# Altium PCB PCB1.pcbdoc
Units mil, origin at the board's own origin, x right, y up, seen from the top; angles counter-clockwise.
Board outline 4130 x 3879.64 mil, 2 copper layers (Top Layer, Bottom Layer); 142 components, 79 nets, 510 pads, 190 vias.
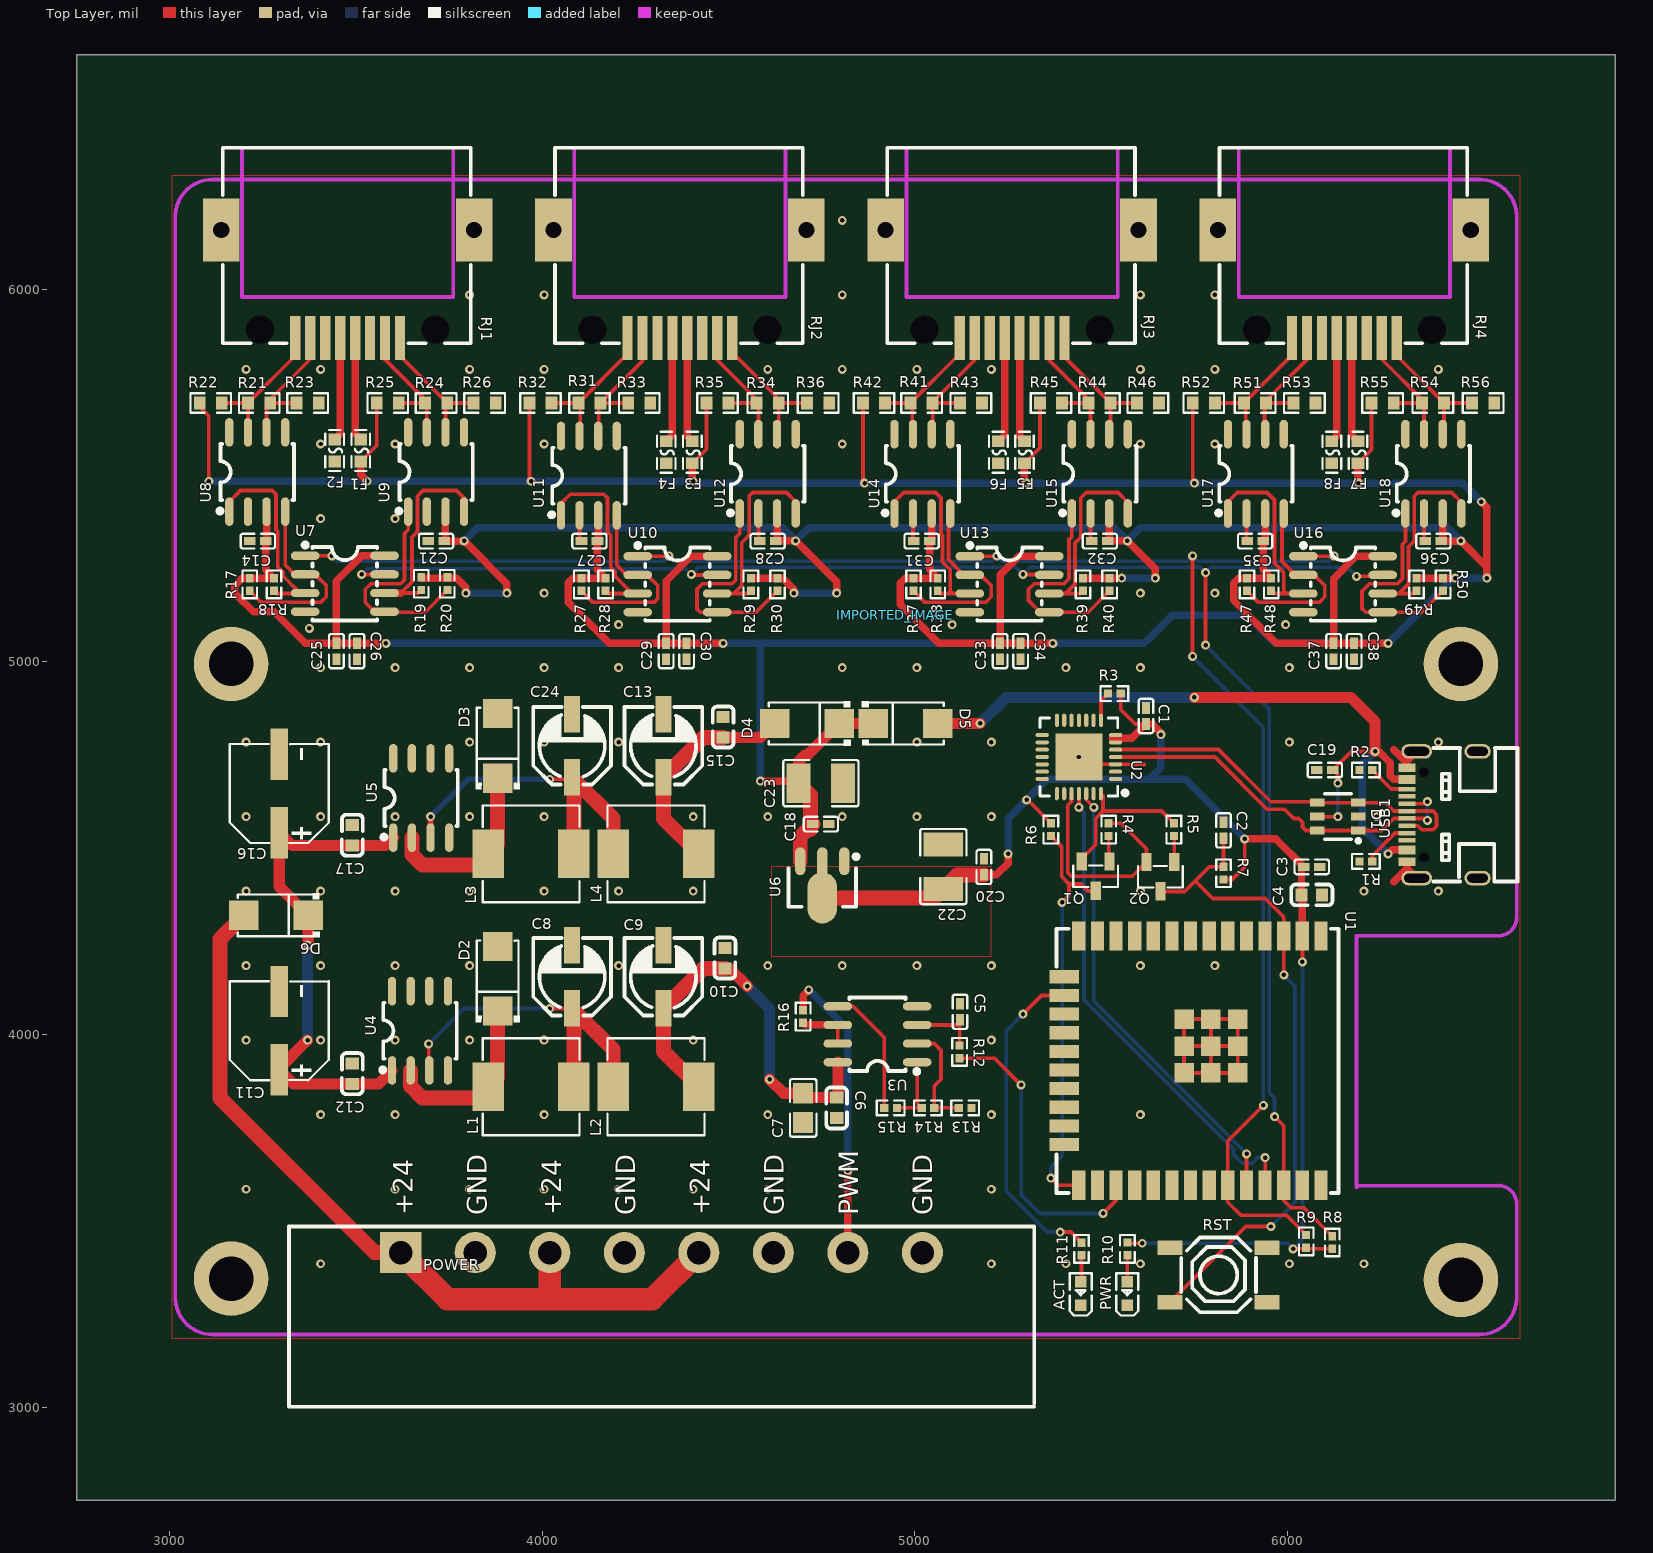
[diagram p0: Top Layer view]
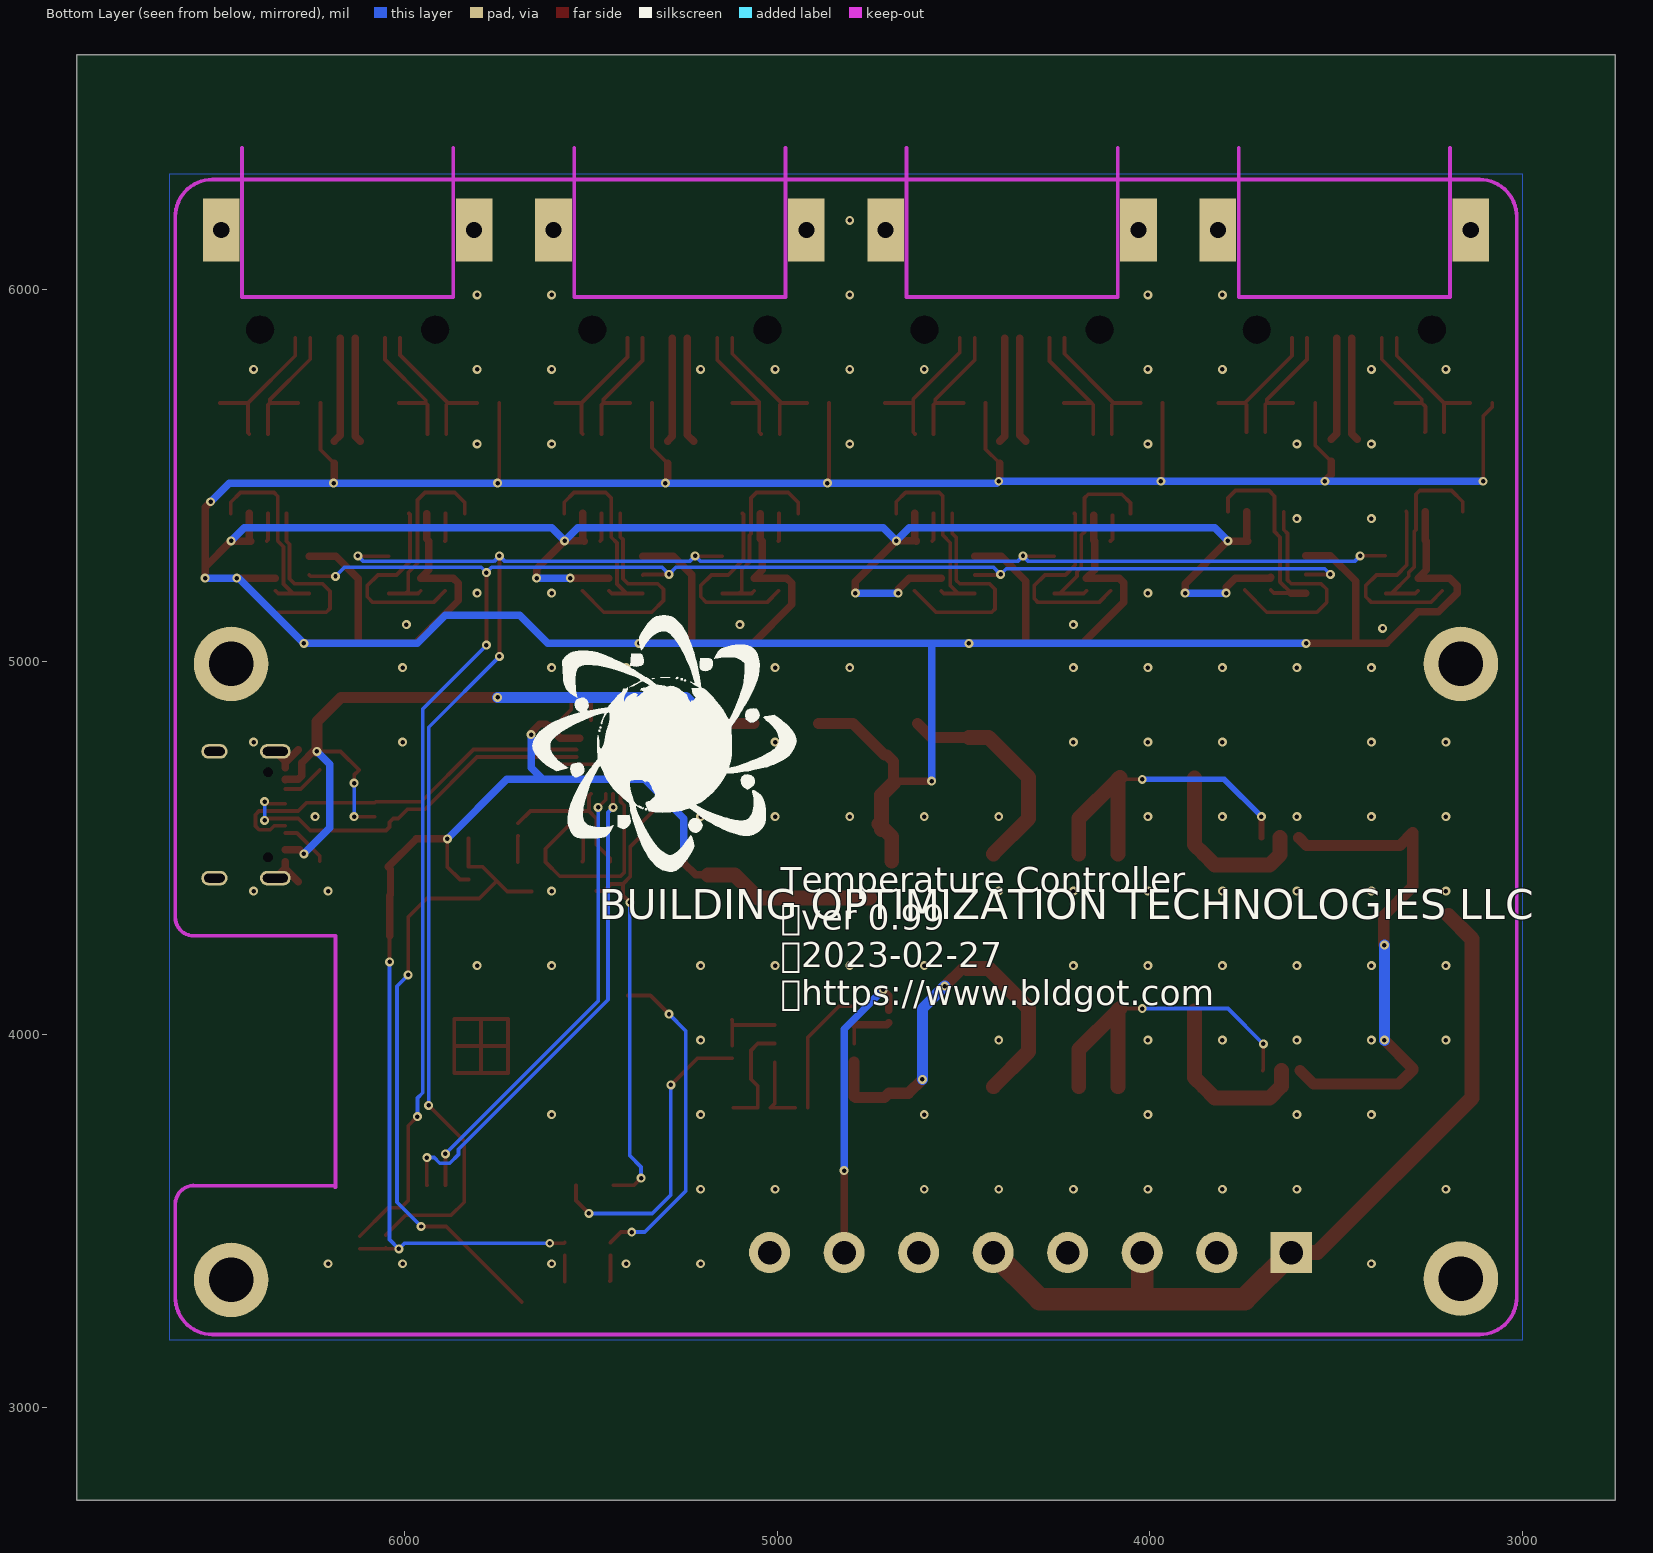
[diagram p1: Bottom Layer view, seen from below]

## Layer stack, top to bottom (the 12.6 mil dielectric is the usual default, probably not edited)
Top Layer: signal copper (thickness not stored)
Dielectric: dielectric 12.6, FR-4, Dk 4.8
Bottom Layer: signal copper (thickness not stored)

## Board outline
6880,2750 2750,2750 2750,6629.64 6880,6629.64

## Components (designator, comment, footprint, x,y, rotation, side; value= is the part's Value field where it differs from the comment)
ACT "19-217/BHC-ZL1M2RY/3T" LED0603-RD 5445,3304.45 r90 top
C1 "CAP_0402" C0402 5620,4854.45 r90 top
C2 "CAP_0402" C0402 5828.08,4547.53 r90 top
C3 "CAP_0402" C0402 6065,4449.45 r0 top
C4 "CL10A106KP8NNNC" C0603 6065,4374.45 r180 top
C5 "CAP_0402" C0402 5121.04,4060.68 r90 top
C6 "CC0603KRX7R9BB104" C0603 4789.94,3802.91 r90 top
C7 "GRM21BR61H106KE43L" C0805 4699.94,3802.91 r90 top
C8 "CK1C470M-CRD54" CAP-SMD_BD5.0-L5.3-W5.3-RD 4080,4154.45 r270 top
C9 "CK1C470M-CRD54" CAP-SMD_BD5.0-L5.3-W5.3-RD 4325,4154.45 r270 top
C10 "CC0603KRX7R9BB104" C0603 4490,4204.45 r270 top
C11 "CS1H470M-CRE77" CAP-SMD_BD6.3-L6.6-W6.6-FD 3294.05,4009.89 r90 top
C12 "CC0603KRX7R9BB104" C0603 3490,3894.45 r270 top
C13 "CS1A101M-CRD54" CAP-SMD_BD5.0-L5.3-W5.3-RD 4325,4774.45 r270 top
C14 "CAP_0402" C0402 3236.58,5323.89 r0 top
C15 "CC0603KRX7R9BB104" C0603 4485,4824.45 r270 top
C16 "CS1H470M-CRE77" CAP-SMD_BD6.3-L6.6-W6.6-FD 3294.05,4646.35 r90 top
C17 "CC0603KRX7R9BB104" C0603 3490,4534.45 r270 top
C18 "CAP_0402" C0402 4747.61,4564.21 r0 top
C19 "CAP_0402" C0402 6100,4709.45 r180 top
C20 "CAP_0402" C0402 5185,4449.45 r90 top
C21 "CAP_0402" C0402 3714.9,5323.89 r0 top
C22 "JMK325BJ107MM-T" C1210 5076.35,4450.47 r270 top
C23 "HMK325C7475KMHPE" C1210 4747.61,4674.21 r180 top
C24 "CS1A101M-CRD54" CAP-SMD_BD5.0-L5.3-W5.3-RD 4080,4774.45 r270 top
C25 "CAP_0402" C0402 3447.37,5028.61 r90 top
C26 "CAP_0402" C0402 3502.37,5028.61 r270 top
C27 "CAP_0402" C0402 4126.58,5323.89 r0 top
C28 "CAP_0402" C0402 4604.9,5323.89 r0 top
C29 "CAP_0402" C0402 4332.37,5028.61 r90 top
C30 "CAP_0402" C0402 4387.37,5028.61 r270 top
C31 "CAP_0402" C0402 5017.91,5323.89 r0 top
C32 "CAP_0402" C0402 5496.24,5323.89 r0 top
C33 "CAP_0402" C0402 5228.71,5028.61 r90 top
C34 "CAP_0402" C0402 5283.71,5028.61 r270 top
C35 "CAP_0402" C0402 5912.91,5323.89 r0 top
C36 "CAP_0402" C0402 6391.24,5323.89 r0 top
C37 "CAP_0402" C0402 6123.71,5028.61 r90 top
C38 "CAP_0402" C0402 6178.71,5028.61 r270 top
D1 "USBLC6-2SC6_C7519" SOT-23-6_L2.9-W1.6-P0.95-LS2.8-BR 6135,4584.45 r0 top
D2 "SS34_C8678" SMA_L4.3-W2.6-LS5.2-RD 3880,4149.45 r90 top
D3 "SS34_C8678" SMA_L4.3-W2.6-LS5.2-RD 3880,4774.45 r90 top
D4 "SS34_C8678" SMA_L4.3-W2.6-LS5.2-RD 4710,4834.45 r180 top
D5 "SS34_C8678" SMA_L4.3-W2.6-LS5.2-RD 4975,4834.45 r0 top
D6 "SS34_C8678" SMA_L4.3-W2.6-LS5.2-RD 3285,4319.45 r180 top
F1 "0494001.NR" F0603 3512.64,5567.23 r90 top
F2 "0494001.NR" F0603 3442.64,5567.23 r90 top
F3 "0494001.NR" F0603 4402.64,5562.23 r90 top
F4 "0494001.NR" F0603 4332.64,5562.23 r90 top
F5 "0494001.NR" F0603 5293.97,5562.23 r90 top
F6 "0494001.NR" F0603 5223.97,5562.23 r90 top
F7 "0494001.NR" F0603 6188.97,5562.23 r90 top
F8 "0494001.NR" F0603 6118.97,5562.23 r90 top
IMPORTED_IMAGE "IMPORTED_IMAGE" IMPORTED_IMAGE 4947.73,5124.45 r0 top
L1 "SMMS0650-680M" IND-SMD_L7.1-W6.6 3970,3859.45 r180 top
L2 "SMMS0650-680M" IND-SMD_L7.1-W6.6 4305,3859.45 r180 top
L3 "SMMS0650-680M" IND-SMD_L7.1-W6.6 3970,4484.45 r180 top
L4 "SMMS0650-680M" IND-SMD_L7.1-W6.6 4305,4484.45 r180 top
POWER "2ETYRM-5.08-08P-14-00AH" CONN-TH_2ETYRM-5.08-08P-14-00AH 4320,3414.45 r0 top
PWR "19-217/GHC-YR1S2/3T" LED0603-RD 5570,3304.45 r90 top
Q1 "S9013 J3_C6749" SOT-23-3_L2.9-W1.3-P1.90-LS2.4-BR 5485,4424.45 r90 top
Q2 "S9013 J3_C6749" SOT-23-3_L2.9-W1.3-P1.90-LS2.4-BR 5658.87,4423.11 r90 top
R1 "Res_0402" R0402 6210,4464.45 r0 top
R2 "Res_0402" R0402 6210,4709.45 r180 top
R3 "Res_0402" R0402 5535,4914.45 r180 top
R4 "Res_0402" R0402 5520,4549.45 r270 top
R5 "Res_0402" R0402 5695,4549.45 r270 top
R6 "Res_0402" R0402 5365,4549.45 r90 top
R7 "Res_0402" R0402 5828.08,4432.53 r270 top
R8 "Res_0402" R0402 6120,3441.49 r270 top
R9 "Res_0402" R0402 6050,3444.45 r270 top
R10 "Res_0402" R0402 5570,3424.45 r90 top
R11 "Res_0402" R0402 5447.14,3424.16 r90 top
R12 "Res_0402" R0402 5119.94,3952.91 r90 top
R13 "AR02BTC1002" R0402 5134.94,3802.91 r180 top
R14 "AR02BTC1002" R0402 5034.94,3802.91 r180 top
R15 "Res_0402" R0402 4934.94,3802.91 r180 top
R16 "Res_0402" R0402 4699.94,4047.91 r90 top
R17 "Res_0402" R0402 3214.85,5207.48 r90 top
R18 "Res_0402" R0402 3279.79,5207.48 r90 top
R19 "Res_0402" R0402 3675,5209.45 r90 top
R20 "Res_0402" R0402 3745,5209.45 r90 top
R21 "Res_0603" R0603 3240.19,5694.6 r180 top
R22 "Res_0603" R0603 3110.19,5694.6 r180 top
R23 "Res_0603" R0603 3370.19,5694.6 r180 top
R24 "Res_0603" R0603 3715.19,5694.6 r180 top
R25 "Res_0603" R0603 3585.19,5694.6 r180 top
R26 "Res_0603" R0603 3845.19,5694.6 r180 top
R27 "Res_0402" R0402 4104.85,5207.48 r90 top
R28 "Res_0402" R0402 4169.79,5207.48 r90 top
R29 "Res_0402" R0402 4559.74,5207.48 r90 top
R30 "Res_0402" R0402 4631.06,5207.48 r90 top
R31 "Res_0603" R0603 4126.58,5694.6 r180 top
R32 "Res_0603" R0603 3995.19,5694.6 r180 top
R33 "Res_0603" R0603 4260.19,5694.6 r180 top
R34 "Res_0603" R0603 4604.9,5694.6 r180 top
R35 "Res_0603" R0603 4470.19,5694.6 r180 top
R36 "Res_0603" R0603 4740.19,5694.6 r180 top
R37 "Res_0402" R0402 4996.19,5207.48 r90 top
R38 "Res_0402" R0402 5061.13,5207.48 r90 top
R39 "Res_0402" R0402 5451.08,5207.48 r90 top
R40 "Res_0402" R0402 5522.4,5207.48 r90 top
R41 "Res_0603" R0603 5017.91,5694.6 r180 top
R42 "Res_0603" R0603 4890.19,5694.6 r180 top
R43 "Res_0603" R0603 5150.19,5694.6 r180 top
R44 "Res_0603" R0603 5495.19,5694.6 r180 top
R45 "Res_0603" R0603 5365.19,5694.6 r180 top
R46 "Res_0603" R0603 5625.19,5694.6 r180 top
R47 "Res_0402" R0402 5891.19,5207.48 r90 top
R48 "Res_0402" R0402 5956.13,5207.48 r90 top
R49 "Res_0402" R0402 6346.08,5207.48 r90 top
R50 "Res_0402" R0402 6417.4,5207.48 r90 top
R51 "Res_0603" R0603 5912.91,5694.6 r180 top
R52 "Res_0603" R0603 5775.19,5694.6 r180 top
R53 "Res_0603" R0603 6045.19,5694.6 r180 top
R54 "Res_0603" R0603 6390.19,5694.6 r180 top
R55 "Res_0603" R0603 6255.19,5694.6 r180 top
R56 "Res_0603" R0603 6524.85,5694.6 r180 top
RJ1 "MJ88-B011-JRVS1-P" RJ45-SMD_MJ88-B011-JRVS1-P. 3477.64,6013.99 r180 top
RJ2 "MJ88-B011-JRVS1-P" RJ45-SMD_MJ88-B011-JRVS1-P. 4369.22,6013.99 r180 top
RJ3 "MJ88-B011-JRVS1-P" RJ45-SMD_MJ88-B011-JRVS1-P. 5260.81,6013.99 r180 top
RJ4 "MJ88-B011-JRVS1-P" RJ45-SMD_MJ88-B011-JRVS1-P. 6152.4,6013.99 r180 top
RST "TS-1187A-B-A-B" SW-SMD_4P-L5.1-W5.1-P3.70-LS6.5-TL-2 5815,3354.45 r180 top
U1 "ESP32-WROOM-32UE-N16_C701346" WIFI-SMD_ESP32-WROOM-32UE 5745,3929.45 r270 top
U2 "CP2102-GMR" WQFN-28_L5.0-W5.0-P0.50-BL-EP3.2 5439.99,4744.45 r90 top
U3 "LM358DR2G" SOIC-8_L5.0-W4.0-P1.27-LS6.0-BL 4899.68,4000.43 r90 top
U4 "XL1509-12E1" SOIC-8_L5.0-W4.0-P1.27-LS6.0-BL 3671.73,4009.71 r0 top
U5 "XL1509-5.0E1" SOIC-8_L5.0-W4.0-P1.27-LS6.0-BL 3675,4634.45 r0 top
U6 "AMS1117-3.3_C2904742" SOT-89-3_L4.5-W2.5-P1.50-LS4.1-BL 4751.35,4415.47 r180 top
U7 "P82B96D" SOIC-8_L5.0-W4.0-P1.27-LS6.1-BL 3470,5209.45 r270 top
U8 "PCA82C251T/YM,118" SOIC-8_L5.0-W4.0-P1.27-LS6.0-BL 3235,5509.45 r0 top
U9 "PCA82C251T/YM,118" SOIC-8_L5.0-W4.0-P1.27-LS6.0-BL 3715,5509.45 r0 top
U10 "P82B96D" SOIC-8_L5.0-W4.0-P1.27-LS6.1-BL 4362.64,5208.16 r270 top
U11 "PCA82C251T/YM,118" SOIC-8_L5.0-W4.0-P1.27-LS6.0-BL 4125,5499.45 r0 top
U12 "PCA82C251T/YM,118" SOIC-8_L5.0-W4.0-P1.27-LS6.0-BL 4604.9,5504.54 r0 top
U13 "P82B96D" SOIC-8_L5.0-W4.0-P1.27-LS6.1-BL 5253.97,5208.16 r270 top
U14 "PCA82C251T/YM,118" SOIC-8_L5.0-W4.0-P1.27-LS6.0-BL 5020,5504.45 r0 top
U15 "PCA82C251T/YM,118" SOIC-8_L5.0-W4.0-P1.27-LS6.0-BL 5496.24,5504.54 r0 top
U16 "P82B96D" SOIC-8_L5.0-W4.0-P1.27-LS6.1-BL 6148.97,5208.16 r270 top
U17 "PCA82C251T/YM,118" SOIC-8_L5.0-W4.0-P1.27-LS6.0-BL 5915,5504.45 r0 top
U18 "PCA82C251T/YM,118" SOIC-8_L5.0-W4.0-P1.27-LS6.0-BL 6391.24,5504.54 r0 top
USB1 "TYPEC-304-ACP16" USB-C-SMD_TYPE-C-16P-1 6415,4589.45 r90 top

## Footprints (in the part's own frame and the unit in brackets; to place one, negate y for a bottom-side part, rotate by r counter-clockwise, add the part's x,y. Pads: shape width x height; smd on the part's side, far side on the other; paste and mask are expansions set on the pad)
C0402 [mm]
  rect 0.79x0.54 smd: 1(-0.545,0) 2(0.545,0)
  silkscreen extent -1.17,-0.5 1.17,0.5
C0603 [mm]
  rect 0.8x0.9 smd: 1(-0.7,0) 2(0.7,0)
  silkscreen extent -1.41,-0.71 1.39,0.72
C0805 [mm]
  rect 1.41x1.35 smd: 1(-1,0) 2(1,0)
  silkscreen extent -1.96,-0.9 1.96,0.9
C1210 [mm]
  rect 1.635x2.7 smd: 1(-1.517,0) 2(1.517,0)
  silkscreen extent -2.56,-1.58 2.56,1.58
CAP-SMD_BD5.0-L5.3-W5.3-RD [mm]
  rect 2.5x1.1 smd: 1(2.15,0) 2(-2.15,0)
  silkscreen extent -2.65,-2.65 2.64,2.65
CAP-SMD_BD6.3-L6.6-W6.6-FD [mm]
  rect 3.5x1.2 smd: 1(-2.67,0) 2(2.67,0)
  silkscreen extent -3.38,-3.38 3.38,3.38
CONN-TH_2ETYRM-5.08-08P-14-00AH [mm]
  rect 2.8x2.8 hole 1.6: 1(-17.78,0)
  round 2.8 hole 1.6: 2(-12.7,0) 3(-7.62,0) 4(-2.54,0) 5(2.54,0) 6(7.62,0) 7(12.7,0) 8(17.78,0)
  silkscreen extent -25.4,-10.5 25.4,1.78
F0603 [mil]
  rect 31.75x34.02 smd: 1(-29.66,0) 2(29.66,0)
  silkscreen extent -55,-25 55,25
IMPORTED_IMAGE [mil]
IND-SMD_L7.1-W6.6 [mm]
  rect 2.15x3.32 smd: 1(-2.913,0) 2(2.913,0)
  silkscreen extent -3.3,-3.3 3.3,3.3
LED0603-RD [mm]
  rect 0.8x0.8 smd: 1(-0.799,-0.003) 2(0.799,0.003)
  silkscreen extent -1.49,-0.75 1.39,0.76
R0402 [mm]
  rect 0.566x0.54 smd: 1(-0.433,0) 2(0.433,0)
  silkscreen extent -0.94,-0.5 0.94,0.5
R0603 [mil]
  rect 31.75x34.02 smd: 1(-29.66,0) 2(29.66,0)
  silkscreen extent -55,-26 55,26
RJ45-SMD_MJ88-B011-JRVS1-P. [mm]
  rect 0.7x3 smd: 1(-3.57,3.684) 2(-2.55,3.684) 3(-1.53,3.684) 4(-0.51,3.684) 5(0.51,3.684) 6(1.53,3.684) 7(2.55,3.684) 8(3.57,3.684)
  rect 2.5x4.3 hole 1.1: 9(8.62,-3.684) 10(-8.62,-3.684)
  Board Outline Layer lines w0.254: 7.2,0.89 -7.2,0.89 ; 7.2,0.89 7.2,-9.271 7.2,0.89 ; 7.2,0.89 -7.2,0.89 ; -7.2,0.89 -7.2,-9.271 -7.2,0.89
  Multi-Layer board cut-out: -6.92,3.117 -6.826,2.704 -6.562,2.374 -6.181,2.19 -5.759,2.19 -5.378,2.374 -5.114,2.704 -5.02,3.117 -5.02,3.117 -5.114,3.529 -5.378,3.859 -5.759,4.043 -6.181,4.043 -6.562,3.859 -6.826,3.529 -6.92,3.117
  Multi-Layer board cut-out: 5.02,3.117 5.114,2.704 5.378,2.374 5.759,2.19 6.181,2.19 6.562,2.374 6.826,2.704 6.92,3.117 6.92,3.117 6.826,3.529 6.562,3.859 6.181,4.043 5.759,4.043 5.378,3.859 5.114,3.529 5.02,3.117
  silkscreen extent -8.38,-9.29 8.51,4.05
SMA_L4.3-W2.6-LS5.2-RD [mm]
  rect 2x2 smd: 1(-2.2,0) 2(2.2,0)
  silkscreen extent -2.98,-1.5 2.6,1.5
SOIC-8_L5.0-W4.0-P1.27-LS6.0-BL [mil]
  oval 22.38x76.78 smd: 1(-75,-106.5) 2(-25,-106.5) 3(25,-106.5) 4(75,-106.5) 5(75,106.5) 6(25,106.5) 7(-25,106.5) 8(-75,106.5)
  silkscreen extent -106,-111 98,75
SOIC-8_L5.0-W4.0-P1.27-LS6.1-BL [mil]
  oval 22.38x76.78 smd: 1(-75,-106.5) 2(-25,-106.5) 3(25,-106.5) 4(75,-106.5) 5(75,106.5) 6(25,106.5) 7(-25,106.5) 8(-75,106.5)
  silkscreen extent -110,-112 98,87
SOT-23-3_L2.9-W1.3-P1.90-LS2.4-BR [mm]
  rect 1.25x0.7 smd: 1(1,-0.95) 2(1,0.95) 3(-1,0)
  silkscreen extent -0.73,-1.53 0.73,1.53
SOT-23-6_L2.9-W1.6-P0.95-LS2.8-BR [mm]
  rect 1x0.55 smd: 1(1.4,-0.95) 2(1.4,0) 3(1.4,0.95) 4(-1.4,0.95) 5(-1.4,0) 6(-1.4,-0.95)
  silkscreen extent -0.9,-1.78 1.52,1.55
SOT-89-3_L4.5-W2.5-P1.50-LS4.1-BL [mm]
  oval 0.7x1.9 smd: 1(-1.501,-1.25) 3(1.501,-1.25)
  oval 2x3.5 smd: 2(0,1.25)
  oval 0.7x2.1 smd: 2(0,-1.151)
  silkscreen extent -2.46,-1.71 2.3,1.85
SW-SMD_4P-L5.1-W5.1-P3.70-LS6.5-TL-2 [mm]
  rect 1.7x1 smd: 1(-3.3,1.85) 2(3.3,1.85) 3(-3.3,-1.85) 4(3.3,-1.85)
  silkscreen extent -2.55,-2.55 2.55,2.55
USB-C-SMD_TYPE-C-16P-1 [mm]
  rect 0.6x1.15 smd: A1B12(-3.2,2.41) A4B9(-2.4,2.41) B1A12(3.2,2.41) B4A9(2.4,2.41)
  rect 0.3x1.15 smd: A5(-1.25,2.41) A6(-0.25,2.41) A7(0.25,2.41) A8(1.25,2.41) B5(1.75,2.41) B6(0.75,2.41) B7(-0.75,2.41) B8(-1.75,2.41)
  oval 1x1.8 hole 0.6 slot 1.4 at 90 deg: EP(-4.32,-2.41) EP(4.32,-2.41)
  oval 1x2.1 hole 0.6 slot 1.7 at 90 deg: EP(-4.32,1.74) EP(4.32,1.74)
  Multi-Layer board cut-out: -2.9,0.915 -2.759,0.947 -2.646,1.037 -2.583,1.168 -2.583,1.312 -2.646,1.443 -2.759,1.533 -2.9,1.565 -2.9,1.565 -3.041,1.533 -3.154,1.443 -3.217,1.312 -3.217,1.168 -3.154,1.037 -3.041,0.947 -2.9,0.915
  Multi-Layer board cut-out: 2.9,0.925 3.041,0.957 3.154,1.047 3.217,1.178 3.217,1.322 3.154,1.453 3.041,1.543 2.9,1.575 2.9,1.575 2.759,1.543 2.646,1.453 2.583,1.322 2.583,1.178 2.646,1.047 2.759,0.957 2.9,0.925
  silkscreen extent -4.55,-5.14 4.55,0.59
WIFI-SMD_ESP32-WROOM-32UE [mm]
  rect 2x0.9 smd: 1(-8.5,8.755) 2(-8.5,7.485) 3(-8.5,6.215) 4(-8.5,4.945) 5(-8.5,3.675) 6(-8.5,2.405) 7(-8.5,1.135) 8(-8.5,-0.135) 9(-8.5,-1.405) 10(-8.5,-2.675) 11(-8.5,-3.945) 12(-8.5,-5.215) 13(-8.5,-6.485) 14(-8.5,-7.755) 25(8.5,-7.755) 26(8.5,-6.485) 27(8.5,-5.215) 28(8.5,-3.945) 29(8.5,-2.675) 30(8.5,-1.405) 31(8.5,-0.135) 32(8.5,1.135) 33(8.5,2.405) 34(8.5,3.675) 35(8.5,4.945) 36(8.5,6.215) 37(8.5,7.485) 38(8.5,8.755)
  rect 0.9x2 smd: 15(-5.715,-8.755) 16(-4.445,-8.755) 17(-3.175,-8.755) 18(-1.905,-8.755) 19(-0.635,-8.755) 20(0.635,-8.755) 21(1.905,-8.755) 22(3.175,-8.755) 23(4.445,-8.755) 24(5.715,-8.755)
  rect 1.33x1.33 smd: 39(-2.835,3.09) 39(-2.835,1.255) 39(-2.835,-0.58) 39(-1,3.09) 39(-1,1.255) 39(-1,-0.58) 39(0.835,3.09) 39(0.835,1.255) 39(0.835,-0.58)
  silkscreen extent -9,-9.27 9.02,9.95
WQFN-28_L5.0-W5.0-P0.50-BL-EP3.2 [mm]
  oval 0.28x0.9 smd: 1(-1.501,-2.5) 2(-1.001,-2.5) 3(-0.501,-2.5) 4(0,-2.5) 5(0.5,-2.5) 6(1.001,-2.5) 7(1.501,-2.5) 15(1.501,2.5) 16(1.001,2.5) 17(0.5,2.5) 18(0,2.5) 19(-0.501,2.5) 20(-1.001,2.5) 21(-1.501,2.5)
  oval 0.9x0.28 smd: 8(2.5,-1.501) 9(2.5,-1.001) 10(2.5,-0.501) 11(2.5,0) 12(2.5,0.5) 13(2.5,1.001) 14(2.5,1.501) 22(-2.5,1.501) 23(-2.5,1.001) 24(-2.5,0.5) 25(-2.5,0) 26(-2.5,-0.501) 27(-2.5,-1.001) 28(-2.5,-1.501)
  rect 3.2x3.2 smd: 29(0,0)
  silkscreen extent -2.65,-3.3 2.65,2.65

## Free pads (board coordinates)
  round 200 hole 120: 1(3165,3344.45) 1(3165,4994.45) 1(6465,3341.21) 1(6465,4994.45)

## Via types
v1: diameter 24, hole 12, Top Layer to Bottom Layer, 107 vias
v2: diameter 24.02, hole 12.01, Top Layer to Bottom Layer, 83 vias

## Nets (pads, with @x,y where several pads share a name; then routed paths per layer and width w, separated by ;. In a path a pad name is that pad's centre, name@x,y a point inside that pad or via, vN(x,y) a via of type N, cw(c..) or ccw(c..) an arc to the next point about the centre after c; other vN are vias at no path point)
3V3: C1.1 C3.1 C4.2 C20.1 C22.2 R3.1 R6.2 R7.2 R8.2 R9.2 R10.2 U1.2 U2.6 U2.7 U6.2 | length 3849
  Top Layer w10: v2(5300,4629.45) 5302.04,4629.45 R6.2 ; R3.1 5552.04,4872.41 5591.46,4832.99 C1.1 ; R10.2 5572.04,3439.45 v2(5610,3439.45) ; R7.2 5851.04,4415.49 5885,4449.45 v2(5885,4524.45) ; v2(6015,3424.45) R9.2@6052.96,3424.45 ; U1.2 6040,4263.78 v2(6040,4194.45) ; R9.2 R9.2@6052.96,3424.45 ; R8.2 R9.2@6052.96,3424.45
  Top Layer w20: C20.1 5218.54,4427.99 5250,4459.45 v2(5250,4484.45) ; 5530,4794.45 5581.46,4794.45 C1.1 5636.46,4832.99 5660,4809.45 v2(5660,4804.45) ; v2(5885,4524.45) 5968.54,4524.45 C3.1 6037.44,4443.35 C4.2 6039.69,4372.2 U1.2
  Top Layer w40: U6.2@4751.35,4366.27 5051.89,4366.27 C22.2 5113.61,4427.99 C20.1
  Bottom Layer w10: v2(5610,3439.45) 6000,3439.45 v2(6015,3424.45) 6040,3449.45 v2(6040,4194.45)
  Bottom Layer w20: v2(5250,4484.45) 5250,4579.45 v2(5300,4629.45) 5355,4684.45 5628.34,4684.45 ; v2(5660,4804.45) 5660,4716.11 5628.34,4684.45 ; v2(5885,4524.45) 5725,4684.45 5628.34,4684.45
5V: C14.2 C18.1 C21.2 C23.2 C25.2 C26.1 C27.2 C28.2 C29.2 C30.1 C31.2 C32.2 C33.2 C34.1 C35.2 C36.2 C37.2 C38.1 D4.1 D5.1 F1.1 F3.1 F5.1 F7.1 R17.2 R18.2 R19.2 R20.2 R22.2 R25.2 R27.2 R28.2 R29.2 R30.2 R32.2 R35.2 R37.2 R38.2 R39.2 R40.2 R42.2 R45.2 R47.2 R48.2 R49.2 R50.2 R52.2 R55.2 U6.3 U7.8 U8.3 U9.3 U10.8 U11.3 U12.3 U13.8 U14.3 U15.3 U16.8 U17.3 U18.3 | length 18749.4
  Top Layer w10: R22.2 3080.53,5683.92 3105,5659.45 v2(3105,5484.45) ; F1.1 3555.53,5580.46 R25.2 ; R32.2 3965.53,5488.92 v2(3970,5484.45) ; F3.1 4440.53,5570.46 R35.2 ; R42.2 4860.53,5483.92 v2(4865,5479.45) ; F5.1 5335.53,5574.13 R45.2 ; R52.2 5745.53,5483.92 v2(5750,5479.45) ; F7.1 6225.53,5569.13 R55.2
  Top Layer w20: U8.3 3260,5325.86 C14.2 3258.04,5246.28 R18.2 R17.2 3195.07,5224.52 3175,5204.45 3175,5184.45 3225,5134.45 3280,5134.45 3364.38,5050.07 C25.2 ; F1.1 3512.64,5501.81 v2(3530,5484.45) ; v2(3580,5049.45) 3579.38,5050.07 C26.1 C25.2 ; U7.8@3581.5,5284.45 3515,5284.45 3447.37,5216.82 C25.2 ; R19.2 3677.04,5224.45 3770,5224.45 3795,5199.45 v2(3795,5184.45) ; U9.3 3740,5327.53 C21.2 3789.45,5323.89 v2(3790,5324.45) 3905,5209.45 v2(3905,5184.45) ; U11.3 4150,5325.86 C27.2 4148.04,5246.28 R28.2 R27.2 4082.22,5224.52 4070,5212.3 4070,5159.45 4179.38,5050.07 C29.2 ; F3.1 4402.64,5486.81 v2(4405,5484.45) ; U10.8 4398.71,5283.16 4332.37,5216.82 C29.2 ; v2(4485,5049.45) 4387.99,5049.45 C30.1 C29.2 ; R29.2 R30.2 4644.93,5224.52 4675,5194.45 v2(4675,5184.45) ; v2(4585,4679.45) C23.2@4682.63,4679.45 ; C28.2 C28.2@4626.92,5324.45 ; U12.3 4629.9,5327.43 C28.2@4626.92,5324.45 ; v2(4790,5184.45) 4790,5214.45 v2(4680,5324.45) C28.2@4626.92,5324.45 ; U14.3 5045,5329.52 C31.2 5039.37,5246.28 R38.2 R37.2 4973.56,5224.52 4960,5210.97 4960,5154.45 5064.38,5050.07 C33.2 ; F5.1 5293.97,5485.47 v2(5300,5479.45) ; U13.8 5278.71,5283.16 5228.71,5233.16 C33.2 ; v2(5370,5049.45) 5369.38,5050.07 C34.1 C33.2 ; R39.2 R40.2 5522.47,5224.45 v2(5555,5224.45) ; C32.2 C32.2@5518.26,5324.45 ; U15.3 5521.24,5327.43 C32.2@5518.26,5324.45 ; v2(5645,5224.45) 5645,5249.45 v2(5570,5324.45) C32.2@5518.26,5324.45 ; U17.3 5940,5329.52 C35.2 5934.37,5246.28 R48.2 R47.2 5868.56,5224.52 5855,5210.97 5855,5164.45 5969.38,5050.07 C37.2 ; F7.1 6188.97,5480.47 v2(6190,5479.45) ; U16.8 6183.71,5283.16 6123.71,5223.16 C37.2 ; v2(6270,5049.45) 6269.38,5050.07 C38.1 C37.2 ; R49.2 R50.2 6417.47,5224.45 v2(6450,5224.45) ; U18.3 6416.24,5327.43 C36.2 6464.45,5323.89 v2(6465,5324.45) 6535,5254.45 ; v2(6520,5429.45) 6535,5414.45 6535,5254.45 ; v2(6535,5224.45) 6535,5254.45
  Top Layer w30: C23.2 4687.87,4732.32 4705,4749.45 4711.61,4749.45 D4.1 D5.1
  Top Layer w40: C23.2 4720,4642.08 C18.1@4720,4558.05 ; U6.3 4692.25,4530.31 C18.1@4720,4558.05 ; 4720,4549.45 C18.1@4720,4558.05 ; C18.1 C18.1@4720,4558.05
  Bottom Layer w20: v2(3105,5484.45) v2(3530,5484.45) v2(3970,5484.45) v2(4405,5484.45) 4410,5479.45 v2(4865,5479.45) v2(5300,5479.45) v2(5750,5479.45) v2(6190,5479.45) 6470,5479.45 v2(6520,5429.45) ; v2(3580,5049.45) v2(4485,5049.45) v2(5370,5049.45) 5615,5049.45 5690,5124.45 5890,5124.45 5965,5049.45 v2(6270,5049.45) 6445,5224.45 v2(6450,5224.45) v2(6535,5224.45) ; v2(3790,5324.45) 3825,5359.45 4645,5359.45 v2(4680,5324.45) 4715,5359.45 5535,5359.45 v2(5570,5324.45) 5605,5359.45 6430,5359.45 v2(6465,5324.45) ; v2(3795,5184.45) v2(3905,5184.45) ; v2(4585,4679.45) 4585,5049.41 ; v2(4675,5184.45) v2(4790,5184.45) ; v2(5555,5224.45) v2(5645,5224.45)
12V: C6.2 C7.2 C9.1 C10.2 L2.1 U3.8 | length 1110
  Top Layer w30: C10.2 4502.56,4176.89 v2(4550,4129.45) ; v2(4610,3879.45) 4647.17,3842.28 C7.2 4711.75,3830.47 C6.2 4793.18,3833.71 U3.8
  Top Layer w40: L2.1 4325,3954.13 C9.1 4432.09,4176.89 C10.2
  Bottom Layer w30: v2(4550,4129.45) 4610,4069.45 v2(4610,3879.45)
$1N2119: R1.2 USB1.A5 | length 132.8
  Top Layer w10: R1.2 6227.04,4478.59 6288.69,4540.24 USB1.A5
$1N2138: R2.1 USB1.B5 | length 114.2
  Top Layer w10: R2.1 6278.14,4658.35 USB1.B5
$1N3272: R3.2 U2.8 | length 79.4
  Top Layer w10: U2.8 5499.1,4895.59 R3.2
$1N3861: Q1.1 R4.2 | length 69.6
  Top Layer w10: R4.2 5520,4466.22 Q1.1
$1N3903: Q2.1 R5.2 | length 70.4
  Top Layer w10: R5.2 5696.27,4531.14 Q2.1
$1N6060: PWR.2 R10.1 | length 71.5
  Top Layer w10: PWR.2 5570,3336.06 R10.1
$1N7451: ACT.2 R11.1 | length 70
  Top Layer w10: R11.1 5447.14,3339.84 ACT.2@5449.04,3337.93
$1N7816: C5.1 R12.2 U3.3 | length 183.6
  Top Layer w10: U3.3 5119.69,4025.43 C5.1@5119.94,4025.68 ; R12.2 C5.1@5119.94,4025.68 ; C5.1 5119.94,4038.12 C5.1@5119.94,4025.68
$1N8177: R13.2 R14.1 U3.2 | length 298.9
  Top Layer w10: U3.2 5051.57,3975.43 5070,3957 5070,3879.45 5051.98,3861.42 R14.1 R13.2
$1N8252: R14.2 R15.1 U3.1 | length 193.3
  Top Layer w10: R15.1 R14.2 5006.18,3814.63 U3.1
$1N8361: R15.2 U3.5 | length 348.1
  Top Layer w10: U3.5 4834.02,4075.43 4917.9,3991.55 R15.2
$1N8403: R16.1 U3.6 U3.7 | length 145.5
  Top Layer w10: U3.7 U3.6
  Top Layer w20: R16.1 4705.38,4025.43 U3.6
$1N10884: C8.1 L1.1 L2.2 U4.3 | length 958.2
  Top Layer w10: v2(3695,3974.45) 3695,3904.94 U4.3 ; v2(4020,4069.45) 4020.35,4069.8 C8.1
  Top Layer w40: C8.1 C8.1@4084.68,4065.11 ; L1.1 C8.1@4084.68,4065.11 ; L2.2 4190.32,3959.47 C8.1@4084.68,4065.11
  Bottom Layer w10: v2(3695,3974.45) 3790,4069.45 v2(4020,4069.45)
$1N10885: D2.1 L1.2 U4.2 | length 490
  Top Layer w40: U4.2 3646.73,3860.78 3678.07,3829.45 3825.32,3829.45 L1.2 3880,3884.13 D2.1
$1N14811: D3.1 L3.2 U5.2 | length 488.4
  Top Layer w40: U5.2 3650,4482.56 3678.11,4454.45 3825.32,4454.45 L3.2 3880,4509.13 D3.1
$1N14814: C24.1 L3.1 L4.2 U5.3 | length 931.8
  Top Layer w10: v2(4020,4684.45) 4074.65,4684.45 C24.1
  Top Layer w15: U5.3 v2(3700,4584.45)
  Top Layer w40: C24.1 C24.1@4084.68,4685.11 ; L3.1 C24.1@4084.68,4685.11 ; L4.2 4190.32,4579.47 C24.1@4084.68,4685.11
  Bottom Layer w15: v2(3700,4584.45) 3800,4684.45 v2(4020,4684.45)
$1N25354: C13.1 C15.2 D4.2 L4.1 | length 602.9
  Top Layer w30: C15.2 4585.83,4796.89 D4.2
  Top Layer w40: L4.1 4325,4579.13 C13.1 4432.09,4796.89 C15.2
$2N23600: F1.2 RJ1.4 | length 278.3
  Top Layer w20: RJ1.4 3497.72,5611.81 F1.2
$2N23659: F2.2 RJ1.5 | length 278.3
  Top Layer w20: F2.2 3457.56,5611.81 RJ1.5
$2N24288: F3.2 RJ2.4 | length 282.6
  Top Layer w20: RJ2.4 4389.3,5605.22 F3.2
$2N24289: F4.2 RJ2.5 | length 283.9
  Top Layer w20: F4.2 4349.14,5608.4 RJ2.5
$2N24625: F5.2 RJ3.4 | length 282.5
  Top Layer w20: RJ3.4 5280.89,5604.97 F5.2
$2N24626: F6.2 RJ3.5 | length 284
  Top Layer w20: F6.2 5240.73,5608.65 RJ3.5
$2N24962: F7.2 RJ4.4 | length 283.9
  Top Layer w20: RJ4.4 6172.48,5608.38 F7.2
$2N24963: F8.2 RJ4.5 | length 282.6
  Top Layer w20: F8.2 6132.32,5605.23 RJ4.5
$2N27234: D6.2 POWER.1 POWER.3 POWER.5 | length 2202.4
  Top Layer w40: D6.2 3135,4256.06 3135,3829.45 3550,3414.45 POWER.1
  Top Layer w60: POWER.1 3745,3289.45 4018.33,3289.45 ; POWER.3 4020,3291.11 4018.33,3289.45 ; POWER.5 4295,3289.45 4018.33,3289.45
DSCL1_N: R24.1 R26.2 RJ1.1 U9.6 | length 378
  Top Layer w10: RJ1.1 3618.19,5821.26 R24.1 ; U9.6@3740,5616.13 3740,5689.75 R24.1 ; R26.2 R24.1
DSCL1_P: R24.2 R25.1 RJ1.2 U9.7 | length 370
  Top Layer w10: RJ1.2 3578.03,5811.42 3685.53,5703.92 R24.2 ; R25.1 R24.2 ; U9.7@3689.9,5616.04 3689.9,5690.22 R24.2
DSCL2_N: R34.1 R36.2 RJ2.1 U12.6 | length 387.5
  Top Layer w10: RJ2.1 4509.77,5829.67 4634.56,5704.88 R34.1 ; U12.6 4634.56,5615.7 R34.1 ; R36.2 R34.1
DSCL2_P: R34.2 R35.1 RJ2.2 U12.7 | length 379
  Top Layer w10: RJ2.2 4469.61,5809.83 4575.24,5704.2 R34.2 ; R35.1 R34.2 ; U12.7 4579.9,5689.94 R34.2
DSCL3_N: R44.1 R46.2 RJ3.1 U15.6 | length 381.3
  Top Layer w10: RJ3.1 5401.36,5818.09 R44.1 ; U15.6 5524.85,5614.65 R44.1 ; R46.2 R44.1
DSCL3_P: R44.2 R45.1 RJ3.2 U15.7 | length 374.2
  Top Layer w10: RJ3.2 5361.2,5808.25 5465.53,5703.92 R44.2 ; R45.1 R44.2 ; U15.7 5471.24,5688.89 R44.2
DSCL4_N: R54.1 R56.2 RJ4.1 U18.6 | length 387.3
  Top Layer w10: RJ4.1 6292.95,5821.5 R54.1 ; U18.6 6419.85,5614.65 R54.1 ; R56.2 R54.1
DSCL4_P: R54.2 R55.1 RJ4.2 U18.7 | length 380.6
  Top Layer w10: RJ4.2 6252.79,5811.66 6360.53,5703.92 R54.2 ; R55.1 R54.2 ; U18.7 6366.24,5688.89 R54.2
DSDA1_N: R21.1 R23.2 RJ1.7 U8.6 | length 372.8
  Top Layer w10: U8.6@3261.58,5616.04 3260,5617.61 3260,5684.75 R21.1 ; R23.2 R21.1 ; RJ1.7 3377.24,5811.68 3269.85,5704.3 R21.1
DSDA1_P: R21.2 R22.1 RJ1.8 U8.7 | length 375.7
  Top Layer w10: R22.1 R21.2 ; U8.7@3210,5616.55 3210,5694.07 R21.2 ; RJ1.8 3337.09,5821.15 R21.2
DSDA2_N: R31.1 R33.2 RJ2.7 U11.6 | length 380.8
  Top Layer w10: U11.6@4151.58,5611.04 4151.58,5689.94 R31.1 ; R33.2 R31.1 ; RJ2.7 4268.82,5807.19 R31.1
DSDA2_P: R31.2 R32.1 RJ2.8 U11.7 | length 386.5
  Top Layer w10: R32.1 R31.2 ; U11.7@4101.58,5611.04 4101.58,5689.94 R31.2 ; RJ2.8 4228.67,5826.36 R31.2
DSDA3_N: R41.1 R43.2 RJ3.7 U14.6 | length 379.6
  Top Layer w10: U14.6@5042.91,5611.04 5047.57,5615.7 R41.1 ; R43.2 R41.1 ; RJ3.7 5160.41,5809.86 5047.57,5697.02 R41.1
DSDA3_P: R41.2 R42.1 RJ3.8 U14.7 | length 382.9
  Top Layer w10: R42.1 R41.2 ; U14.7@4992.91,5611.04 4992.91,5689.94 R41.2 ; RJ3.8 5120.26,5826.61 R41.2
DSDA4_N: R51.1 R53.2 RJ4.7 U17.6 | length 378.1
  Top Layer w10: U17.6@5937.91,5611.04 5937.91,5689.94 R51.1 ; R53.2 R51.1 ; RJ4.7 6052,5811.45 5942.57,5702.02 R51.1
DSDA4_P: R51.2 R52.1 RJ4.8 U17.7 | length 391.5
  Top Layer w10: R52.1 R51.2 ; U17.7@5887.91,5611.04 5887.91,5689.94 R51.2 ; RJ4.8 6011.85,5823.19 R51.2
DTR: Q1.2 R5.1 U2.28 | length 412.1
  Top Layer w10: Q1.2 5447.6,4472.05 5485,4509.45 5485,4579.45 5505,4599.45 ; U2.28 5505,4640.13 5505,4599.45 ; R5.1 5662.04,4599.45 5505,4599.45
EN: C2.1 Q2.3 R7.1 RST.2 U1.3 | length 1774.5
  Top Layer w10: Q2.3 5724.3,4383.74 5751.99,4411.44 ; RST.2 5887.92,3484.45 v2(5955,3484.45) ; C2.1 R7.1 5790.12,4449.57 5751.99,4411.44 ; v2(5990,4159.45) 5990,4263.78 U1.3 5989.69,4314.76 5940,4364.45 5798.98,4364.45 5751.99,4411.44
  Bottom Layer w10: v2(5955,3484.45) 6020,3549.45 6020,4129.45 v2(5990,4159.45)
GND: ACT.1 C1.2 C2.2 C3.2 C4.1 C5.2 C6.1 C7.1 C8.2 C9.2 C10.1 C11.2 C12.1 C13.2 C14.1 C15.1 C16.2 C17.1 C18.2 C19.2 C20.2 C21.1 C22.1 C23.1 C24.2 C25.1 C26.2 C27.1 C28.1 C29.1 C30.2 C31.1 C32.1 C33.1 C34.2 C35.1 C36.1 C37.1 C38.2 D1.2 D2.2 D3.2 F2.1 F4.1 F6.1 F8.1 pad.1 POWER.2 POWER.4 POWER.6 POWER.8 PWR.1 R1.1 R2.2 R13.1 R23.1 R26.1 R33.1 R36.1 R43.1 R46.1 R53.1 R56.1 RJ1.9 RJ1.10 RJ2.9 RJ2.10 RJ3.9 RJ3.10 RJ4.9 RJ4.10 RST.3 U1.1 U1.15 U1.38 U1.39 U2.3 U2.29 U3.4 U4.4 U4.5 U4.6 U4.7 U4.8 U5.4 U5.5 U5.6 U5.7 U5.8 U6.1 U7.4 U8.2 U9.2 U10.4 U11.2 U12.2 U13.4 U14.2 U15.2 U16.4 U17.2 U18.2 USB1.A1B12 USB1.B1A12 USB1.EP | length 1708.1
  Top Layer w10: U11.2 4100,5329.01 C27.1 ; U12.2 4579.9,5327.43 C28.1 ; U14.2 4995,5325.35 C31.1 ; v2(5440,4744.45) 5459.7,4724.75 U2.3 5614.7,4724.75 5615,4724.45 ; U15.2 5471.24,5327.43 C32.1 ; U17.2 5890,5325.35 C35.1 ; U18.2 6366.24,5327.43 C36.1 ; U1.39@5722.16,3968.82 U1.39@5794.41,3968.82 ; U1.39@5722.16,3968.82 5722.16,3896.58 U1.39@5794.41,3896.58 ; U1.39@5722.16,3968.82 5722.16,4041.06 U1.39@5794.41,4041.06 ; U1.39@5794.41,3896.58 U1.39@5794.41,3968.82 ; U1.39@5794.41,3896.58 5866.65,3896.58 U1.39@5866.65,3968.82 ; U1.39@5794.41,3968.82 U1.39@5794.41,4041.06 ; U1.39@5794.41,3968.82 U1.39@5866.65,3968.82 ; U1.39@5794.41,4041.06 5866.65,4041.06 U1.39@5866.65,3968.82
  Top Layer w20: 6285,4409.45 6320.11,4444.56 6320.11,4445.75 ; 6285,4764.45 6320.11,4729.33 ; USB1.A1B12 6320.11,4445.75 ; USB1.B1A12 6320.11,4729.33 ; USB1.EP@6346.49,4419.37 6320.11,4445.75 ; USB1.EP@6346.49,4759.53 6320.11,4733.15 6320.11,4729.33
  other v1: 3405,3384.45 5205,3384.45 5405,3384.45 5605,3384.45 6005,3384.45 6205,3384.45 3205,3584.45 3605,3584.45 3805,3584.45 4005,3584.45 4205,3584.45 4405,3584.45 4605,3584.45 5005,3584.45 5205,3584.45 3405,3784.45 3605,3784.45 4005,3784.45 4605,3784.45 5205,3784.45 5605,3784.45 3205,3984.45 3405,3984.45 3605,3984.45 3805,3984.45 4005,3984.45 4405,3984.45 5205,3984.45 3205,4184.45 3405,4184.45 3605,4184.45 3805,4184.45 4005,4184.45 4205,4184.45 4605,4184.45 4805,4184.45 5005,4184.45 5205,4184.45 5605,4184.45 5805,4184.45 3205,4384.45 3405,4384.45 3605,4384.45 3805,4384.45 4005,4384.45 4205,4384.45 4405,4384.45 5605,4384.45 6205,4384.45 6405,4384.45 3205,4584.45 3405,4584.45 3605,4584.45 3805,4584.45 4005,4584.45 4405,4584.45 4605,4584.45 4805,4584.45 5005,4584.45 5205,4584.45 3205,4784.45 3405,4784.45 3805,4784.45 4005,4784.45 4205,4784.45 5005,4784.45 5205,4784.45 6005,4784.45 6405,4784.45 3405,4984.45 3605,4984.45 3805,4984.45 4005,4984.45 4205,4984.45 4805,4984.45 5005,4984.45 5405,4984.45 5605,4984.45 6005,4984.45 4005,5184.45 5605,5184.45 5805,5184.45 3405,5384.45 3605,5384.45 3405,5584.45 3605,5584.45 4005,5584.45 4805,5584.45 5605,5584.45 5805,5584.45 3205,5784.45 3405,5784.45 3805,5784.45 4005,5784.45 4605,5784.45 4805,5784.45 5005,5784.45 5205,5784.45 5605,5784.45 5805,5784.45 6405,5784.45 3805,5984.45 4005,5984.45 4805,5984.45 5605,5984.45 5805,5984.45 4805,6184.45
  other v2: 6240,4584.45 3375,5089.45 4205,5099.45 5100,5099.45 5995,5099.45
IO0: Q1.3 R6.1 U1.25 | length 1120
  Top Layer w10: v2(5365,3614.45) 5384.65,3594.8 U1.25 ; R6.1 5394.3,4503.11 5394.3,4422.82 5413.67,4403.45 ; v2(5395,4354.45) 5413.67,4373.12 5413.67,4403.45 ; Q1.3 5464.22,4385.08 5445.85,4403.45 5413.67,4403.45
  Bottom Layer w10: v2(5365,3614.45) 5365,3644.45 5395,3674.45 v2(5395,4354.45)
IO13: R11.2 U1.16 | length 884.1
  Top Layer w10: v2(5290,4054.45) 5340,4104.45 U1.16 ; v2(5390,3469.45) 5418.89,3469.45 R11.2
  Bottom Layer w10: v2(5290,4054.45) 5245,4009.45 5245,3579.45 5355,3469.45 v2(5390,3469.45)
IO16: R12.1 U1.27 | length 820.1
  Top Layer w10: R12.1 5213.58,3935.87 v2(5285,3864.45) ; v2(5505,3519.45) 5539.69,3554.13 U1.27
  Bottom Layer w10: v2(5285,3864.45) 5285,3569.45 5335,3519.45 v2(5505,3519.45)
IO27: U1.12
RTS: Q2.2 R4.1 U2.24 | length 612.1
  Top Layer w10: U2.24 5420.3,4624.75 5410.3,4614.75 5410.3,4434.45 5420.3,4424.45 5583.43,4424.45 Q2.2 5621.47,4497.98 5552.96,4566.49 R4.1
RX0: U1.34 U2.26 | length 1229.6
  Top Layer w10: U2.26 5459.7,4629.75 v2(5480,4609.45) ; U1.34 5890,3595.11 v2(5890,3679.45)
  Bottom Layer w10: v2(5480,4609.45) 5480,4089.45 v2(5890,3679.45)
SCL: R8.1 U1.36 U7.7 U10.7 U13.7 U16.7 | length 4948.5
  Top Layer w10: v2(3515,5234.45) U7.7@3581.49,5234.45 ; v2(4400,5234.45) 4401.29,5233.16 U10.7 ; v2(5290,5234.45) 5359.18,5234.45 U13.7 ; v2(5780,5044.45) v2(5780,5239.45) ; v2(5965,3779.45) 5989.69,3754.76 U1.36 5990,3594.48 5990,3554.45 6010,3534.45 6044.08,3534.45 R8.1 ; v2(6185,5229.45) 6251.76,5229.45 U16.7
  Bottom Layer w10: v2(3515,5234.45) 3530,5249.45 4385,5249.45 v2(4400,5234.45) 4419,5253.45 5271,5253.45 v2(5290,5234.45) 5309,5253.45 5766,5253.45 v2(5780,5239.45) 5794,5253.45 6161,5253.45 v2(6185,5229.45) ; v2(5780,5044.45) 5951,4873.45 5951,3843.45 5965,3829.45 v2(5965,3779.45)
SCL1_RX: R19.1 U7.6 U9.4 | length 553.3
  Top Layer w10: 3618.71,5183.16 3620,5184.45 ; R19.1 3667.04,5184.45 3620,5184.45 ; U9.4 3790,5439.45 3770,5459.45 3680,5459.45 3665,5444.45 3665,5349.45 3650,5334.45 3650,5214.45 3620,5184.45
  Top Layer w20: U7.6@3581.5,5184.45 3620,5184.45
SCL1_TX: R20.1 U7.5 U9.1 | length 593.4
  Top Layer w10: U9.1 3640,5354.45 3630,5344.45 3630,5219.45 3620,5209.45 3540,5209.45 3525,5194.45 3525,5159.45 3551.29,5133.16 3685.75,5133.16 R20.1
SCL2_RX: R29.1 U10.6 U12.4 | length 542.9
  Top Layer w10: U10.6 4513.71,5183.16 ; R29.1 4552.46,5183.16 4513.71,5183.16 ; U12.4 4679.9,5429.54 4655,5454.45 4565,5454.45 4555,5444.45 4555,5339.45 4535,5319.45 4535,5204.45 4513.71,5183.16
SCL2_TX: R30.1 U10.5 U12.1 | length 594.1
  Top Layer w10: U12.1 4530,5397.94 4530,5344.45 4519,5333.45 4519,5218.45 4510,5209.45 4430,5209.45 4415,5194.45 4415,5141.9 4423.74,5133.16 U10.5 4573.78,5133.16 R30.1
SCL3_RX: R39.1 U13.6 U15.4 | length 540.5
  Top Layer w10: U13.6 5403.71,5183.16 ; R39.1 5443.79,5183.16 5403.71,5183.16 ; U15.4 5571.24,5428.21 5545,5454.45 5460,5454.45 5445,5439.45 5445,5334.45 5429.45,5318.89 5429.45,5208.89 5403.71,5183.16
SCL3_TX: R40.1 U13.5 U15.1 | length 582.6
  Top Layer w10: U15.1 5421.19,5335.63 5413.45,5327.89 5413.45,5222.89 5400,5209.45 5320,5209.45 5305,5194.45 5305,5164.45 5336.29,5133.16 U13.5 5465.12,5133.16 R40.1
SCL4_RX: R49.1 U16.6 U18.4 | length 543.4
  Top Layer w10: U16.6 6298.71,5183.16 ; R49.1 6338.79,5183.16 6298.71,5183.16 ; U18.4 6466.24,5428.21 6440,5454.45 6350,5454.45 6340,5444.45 6340,5324.45 6324.45,5308.89 6324.45,5208.89 6298.71,5183.16
SCL4_TX: R50.1 U16.5 U18.1 | length 592.2
  Top Layer w10: U18.1 6316.24,5323.32 6308.45,5315.52 6308.45,5222.89 6295,5209.45 6220,5209.45 6200,5189.45 6200,5143.24 6210.08,5133.16 U16.5 6360.12,5133.16 R50.1
SDA: R9.1 U1.33 U7.1 U10.1 U13.1 U16.1 | length 5146.5
  Top Layer w10: U7.1@3368.5,5284.45 v2(3435,5284.45) ; U10.1 4338.71,5283.16 v2(4340,5284.45) ; U13.1 5218.71,5283.16 v2(5220,5284.45) ; v2(5745,5014.45) v2(5745,5284.45) ; v2(5935,3809.45) 5839.69,3714.13 U1.33 5839.69,3549.76 5875,3514.45 5997.04,3514.45 R9.1 ; U16.1 6123.71,5283.16 v2(6125,5284.45)
  Bottom Layer w10: v2(3435,5284.45) 3450,5269.45 4325,5269.45 v2(4340,5284.45) 4355,5269.45 5205,5269.45 v2(5220,5284.45) 5235,5269.45 5730,5269.45 v2(5745,5284.45) 5760,5269.45 6110,5269.45 v2(6125,5284.45) ; v2(5745,5014.45) 5935,4824.45 v2(5935,3809.45)
SDA1_RX: R17.1 U7.2 U8.4 | length 531.2
  Top Layer w10: R17.1 3245.84,5159.45 3405,5159.45 3420,5174.45 3420,5204.45 3391.29,5233.16 3366.13,5233.16 3336.29,5233.16 3310,5259.45 3310,5401.46 U8.4@3311.58,5403.04
SDA1_TX: R18.1 U7.3 U8.1 | length 551.2
  Top Layer w10: U8.1 3160,5429.45 3190,5459.45 3275,5459.45 3285,5449.45 3285,5354.45 3290,5349.45 3290,5254.45 3305,5239.45 3305,5229.45 U7.3@3351.29,5183.16 ; R18.1 3287.08,5183.16 U7.3@3351.29,5183.16 ; U7.3@3366.13,5183.16 U7.3@3351.29,5183.16
SDA2_RX: R27.1 U10.2 U11.4 | length 529.2
  Top Layer w10: R27.1 4135.84,5159.45 4300,5159.45 4310,5169.45 4310,5204.45 4281.29,5233.16 U10.2 4226.29,5233.16 4200,5259.45 4200,5396.46 U11.4@4201.58,5398.04
SDA2_TX: R28.1 U10.3 U11.1 | length 538.4
  Top Layer w10: U11.1@4051.58,5398.04 4051.58,5426.02 4075,5449.45 4165,5449.45 4175,5439.45 4175,5348.45 4184,5339.45 4184,5252.82 4195,5241.82 4195,5229.45 U10.3@4241.29,5183.16 ; R28.1 4177.08,5183.16 U10.3@4241.29,5183.16 ; U10.3 U10.3@4241.29,5183.16
SDA3_RX: R37.1 U13.2 U14.4 | length 526.7
  Top Layer w10: R37.1 5027.18,5159.45 5190,5159.45 5205,5174.45 5205,5204.45 5176.29,5233.16 U13.2 5131.29,5233.16 5090,5274.45 5090,5395.12 U14.4@5092.91,5398.04
SDA3_TX: R38.1 U13.3 U14.1 | length 532.8
  Top Layer w10: U14.1@4942.91,5398.04 4942.91,5427.36 4970,5454.45 5055,5454.45 5070,5439.45 5070,5343.45 5074,5339.45 5074,5267.82 5095,5246.82 5095,5190.24 5102.08,5183.16 ; R38.1 5068.41,5183.16 5102.08,5183.16 ; U13.3 5102.08,5183.16
SDA4_RX: R47.1 U16.2 U17.4 | length 529.6
  Top Layer w10: R47.1 5922.18,5159.45 6085,5159.45 6100,5174.45 6100,5204.45 6071.29,5233.16 U16.2 6021.29,5233.16 5985,5269.45 5985,5395.12 U17.4@5987.91,5398.04
SDA4_TX: R48.1 U16.3 U17.1 | length 529.8
  Top Layer w10: U17.1@5837.91,5398.04 5837.91,5427.36 5865,5454.45 5945,5454.45 5965,5434.45 5965,5264.45 5990,5239.45 5990,5190.24 5997.08,5183.16 ; R48.1 5963.41,5183.16 5997.08,5183.16 ; U16.3 5997.08,5183.16
TX0: U1.35 U2.25 | length 1315.9
  Top Layer w10: v2(5440,4609.45) U2.25 ; U1.35 5940,3595.11 v2(5940,3669.45)
  Bottom Layer w10: v2(5440,4609.45) 5454,4595.45 5454,4092.82 5855,3691.82 5855,3677.68 5878.23,3654.45 5905,3654.45 5920,3669.45 v2(5940,3669.45)
USB_N: D1.3 D1.4 U2.5 USB1.A7 USB1.B7 | length 1052.6
  Top Layer w10: U2.5 5538.72,4764.45 5815,4764.45 5955,4624.45 6077.28,4624.45 D1.4 D1.3 6262.6,4621.85 6285.16,4599.29 USB1.A7 6390.16,4599.29 6400,4589.45 6400,4559.45 6390,4549.45 6360,4549.45 6349.53,4559.92 USB1.B7
USB_P: D1.1 D1.6 U2.4 USB1.A6 USB1.B6 | length 1048.8
  Top Layer w10: U2.4 5805,4744.45 5945,4604.45 5991.83,4604.45 6016.83,4579.45 6030,4579.45 6040,4569.45 6040,4556.27 6049.23,4547.05 D1.6 D1.1 6252.6,4547.05 6285.16,4579.61 USB1.A6 6369.84,4579.61 v2(6375,4574.45) ; USB1.B6 6369.53,4618.98 v2(6375,4624.45)
  Bottom Layer w10: v2(6375,4574.45) v2(6375,4624.45)
VOUT: POWER.7 R16.2 | length 809.2
  Top Layer w20: R16.2 4699.94,4104.38 v2(4715,4119.45) ; POWER.7 v2(4820,3634.45)
  Bottom Layer w20: v2(4715,4119.45) 4820,4014.45 v2(4820,3634.45)
VPP: C11.1 C12.2 C16.1 C17.2 D6.1 U4.1 U5.1 | length 1363
  Top Layer w30: v2(3370,3984.45) 3294.05,3908.5 C11.1 3331.94,3866.89 C12.2 3560.41,3866.89 U4.1 ; v2(3370,4239.45) 3371.61,4241.06 D6.1 3294.05,4397 C16.1 3328.39,4506.89 C17.2 3578.94,4506.89 U5.1
  Bottom Layer w30: v2(3370,3984.45) v2(3370,4239.45)
VUSB: C19.1 D1.5 D5.2 USB1.A4B9 USB1.B4A9 | length 2139.1
  Top Layer w10: D1.5 v2(6135,4584.45) ; v2(6135,4674.45) 6135,4695.91 C19.1 6171.46,4759.45 v2(6235,4759.45)
  Top Layer w20: v2(6235,4759.45) 6245,4759.45 6275,4729.45 6275,4694.45 6285,4684.45 6319.6,4684.45 USB1.B4A9 ; v2(6270,4484.45) 6280.51,4494.96 USB1.A4B9
  Top Layer w30: D5.2 v2(5175,4834.45) ; v2(5750,4904.45) 6170,4904.45 6235,4839.45 v2(6235,4759.45)
  Bottom Layer w10: v2(6135,4584.45) v2(6135,4674.45)
  Bottom Layer w20: v2(6235,4759.45) 6200,4724.45 6200,4554.45 v2(6270,4484.45)
  Bottom Layer w30: v2(5175,4834.45) 5245,4904.45 v2(5750,4904.45)
"": RJ1.3 RJ1.6 RJ2.3 RJ2.6 RJ3.3 RJ3.6 RJ4.3 RJ4.6 RST.1 RST.4 U1.4 U1.5 U1.6 U1.7 U1.8 U1.9 U1.10 U1.11 U1.13 U1.14 U1.17 U1.18 U1.19 U1.20 U1.21 U1.22 U1.23 U1.24 U1.26 U1.28 U1.29 U1.30 U1.31 U1.32 U1.37 U2.1 U2.2 U2.9 U2.10 U2.11 U2.12 U2.13 U2.14 U2.15 U2.16 U2.17 U2.18 U2.19 U2.20 U2.21 U2.22 U2.23 U2.27 U8.5 U8.8 U9.5 U9.8 U11.5 U11.8 U12.5 U12.8 U14.5 U14.8 U15.5 U15.8 U17.5 U17.8 U18.5 U18.8 USB1.A8 USB1.B8

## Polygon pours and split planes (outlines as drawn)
3V3 on Top Layer (solid, remove dead copper, pour order 0): 4615,4209.45 5204.6,4209.45 5204.6,4449.45 4615,4449.45
GND on Top Layer (solid, remove dead copper, pour order 1): 3005,3184.45 6625,3184.45 6625,6304.45 3005,6304.45
GND on Bottom Layer (solid, remove dead copper, pour order 2): 3000,3179.45 6630,3179.45 6630,6309.45 3000,6309.45

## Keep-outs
Board Outline Layer:
  lines w10 net "": 6615,3544.36 ccw(c6565,3544.45) 6559.48,3594.14 6189.69,3594.14 6185,3589.45 6185,4264.45 ; 6615,3544.45 6615,3294.45 cw(c6515,3294.45) 6515,3194.45 3115,3194.45 cw(c3115,3294.45) 3015,3294.45 3015,6194.45 cw(c3115,6194.45) 3115,6294.45 6515,6294.45 cw(c6515,6194.45) 6615,6194.45 6615,4314.45 cw(c6565,4314.45) 6564.9,4264.45 6185,4264.45 ; 6185,4264.45 6185,4264.45

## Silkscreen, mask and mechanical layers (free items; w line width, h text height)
Top Silkscreen Layer:
  text "+24" at 3652.24,3515.01 h51.92 r90
  text "GND" at 3851.47,3515.01 h51.92 r90
  text "+24" at 4050.71,3515.01 h51.92 r90
  text "GND" at 4249.94,3515.01 h51.92 r90
  text "+24" at 4449.18,3515.01 h51.92 r90
  text "GND" at 4648.41,3515.01 h51.92 r90
  text "PWM" at 4847.65,3515.01 h51.92 r90
  text "GND" at 5046.88,3515.01 h51.92 r90
Bottom Silkscreen Layer:
  text "BUILDING OPTIMIZATION TECHNOLOGIES LLC" at 5478.13,4309.45 h80
  text "Temperature Controller /  ver 0.99 /  2023-02-27 /  https://www.bldgot.com" at 4990.17,4078.66 h67.38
